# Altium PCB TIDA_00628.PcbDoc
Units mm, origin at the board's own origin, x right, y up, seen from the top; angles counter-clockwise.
Board outline 93.5 x 54.5 mm, 2 copper layers (Top Layer, Bottom Layer), stack 1.644 mm thick; 57 components, 18 nets, 97 pads, 0 vias.
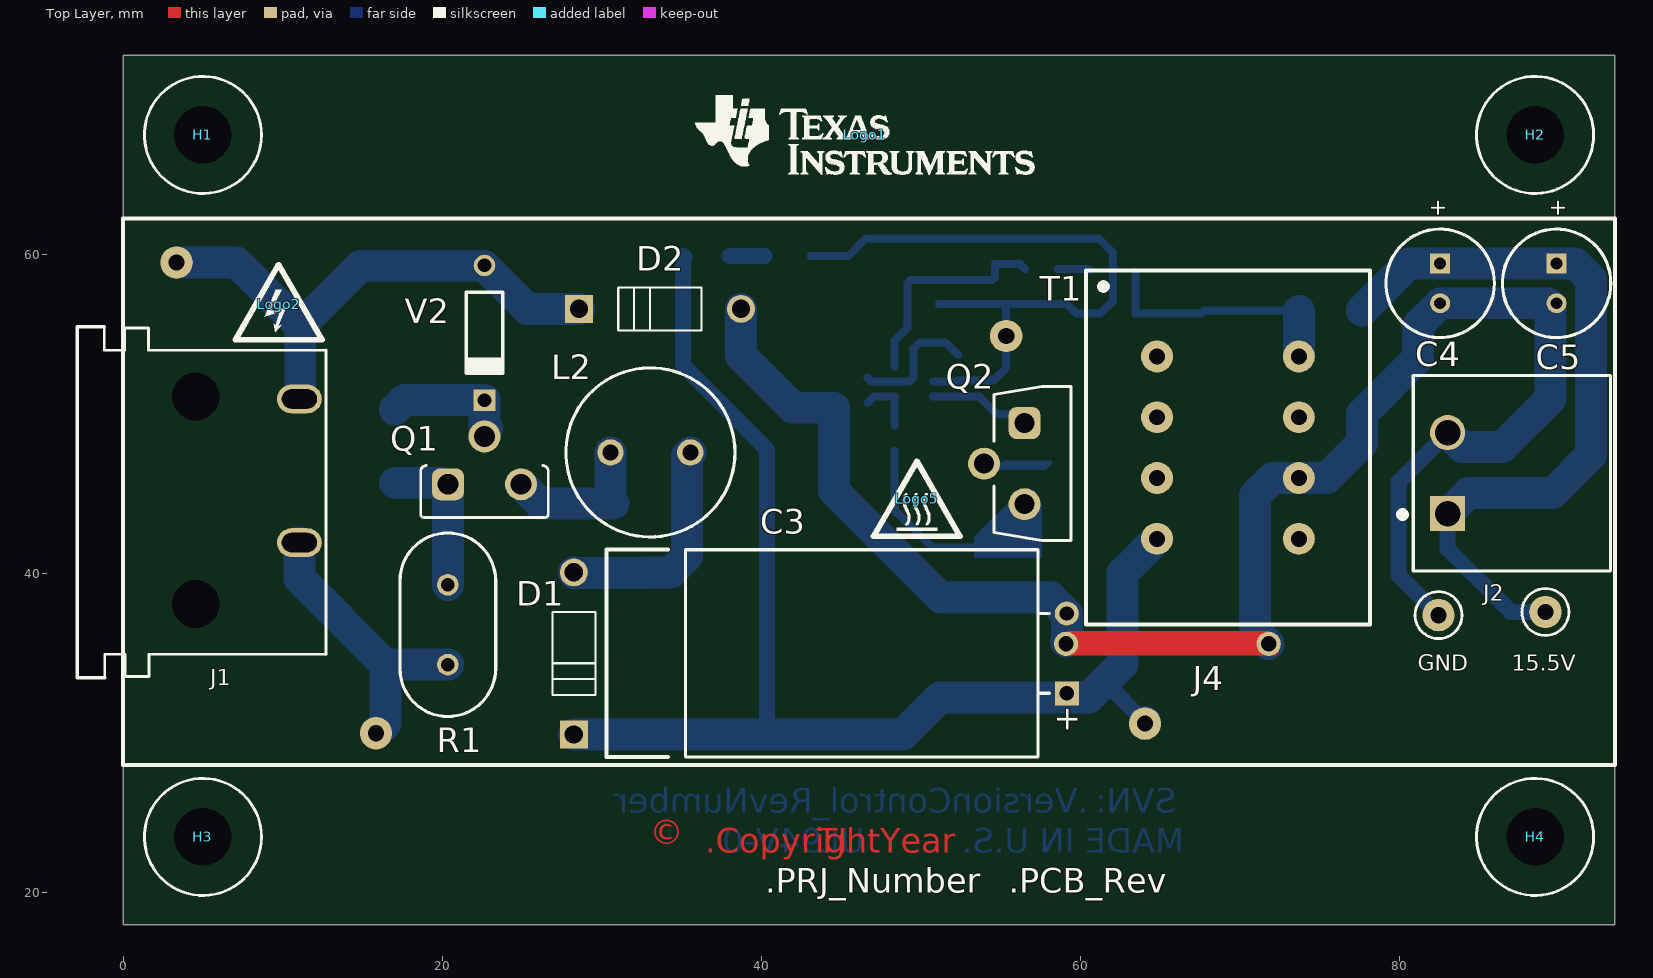
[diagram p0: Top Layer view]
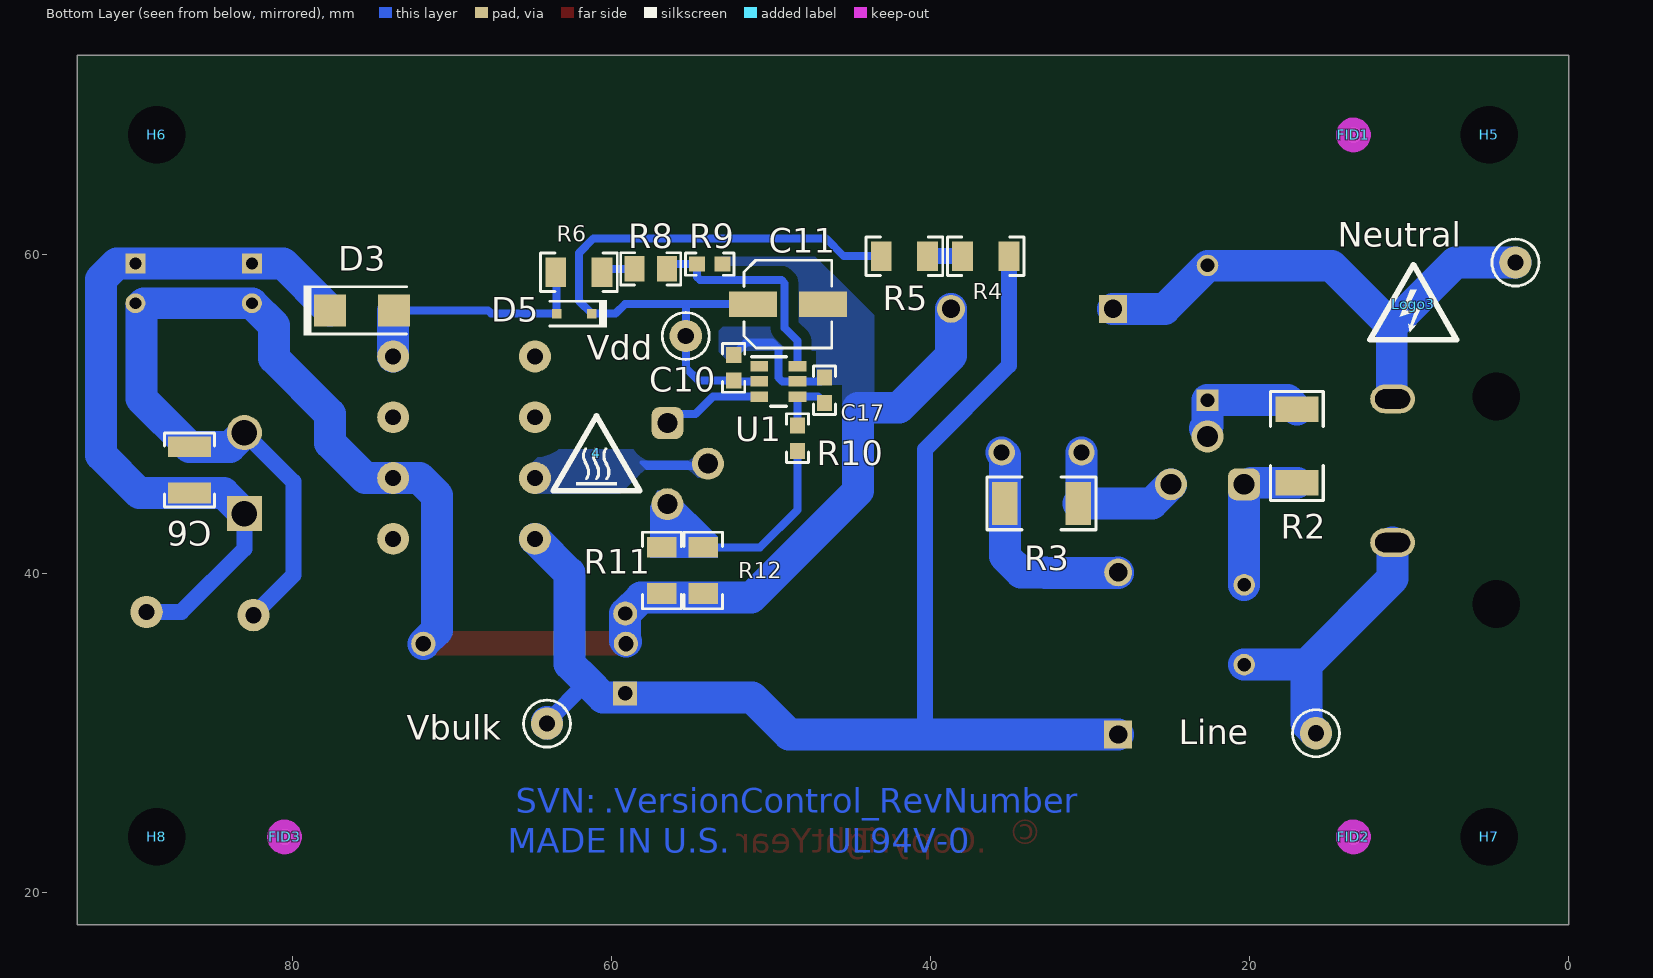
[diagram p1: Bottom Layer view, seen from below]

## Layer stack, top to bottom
Top Solder: solder mask 0.0102, Solder Resist, Dk 3.5
Top Layer: signal copper 0.07
Dielectric1: core 1.5037, FR-4, Dk 4.8
Bottom Layer: signal copper 0.07
Bottom Solder: solder mask 0.0102, Solder Resist, Dk 3.5

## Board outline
0,18 0,72.5 93.5,72.5 93.5,18

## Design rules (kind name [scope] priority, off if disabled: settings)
AcuteAngle [All] p1: minimum=4.50000000000000E+0001 checktracksonly=FALSE
AssemblyTestPointUsage [All] p1: valid=2
Clearance "Schematic Clearance Constraint_9" [InNet('NetD2_1')] p1: gap=2
Clearance "Schematic Clearance Constraint_4" [InNet('NetL2_1')] p2: gap=2
Clearance "Schematic Clearance Constraint_1" [InNet('NetQ1_1')] p3: gap=2
Clearance "Schematic Clearance Constraint" [InNet('NetC3_1')] p4: gap=1.5
Clearance "Schematic Clearance Constraint_6" [InNet('NetQ2_2')] p5: gap=1.5
Clearance "Schematic Clearance Constraint_5" [InNet('NetD1_2')] p6: gap=2
Clearance "Schematic Clearance Constraint_7" [InNet('NetQ1_2')] p7: gap=2
Clearance Clearance_Keepouts [((IsTrack Or IsArc) And Not InPoly) And IsFree and IsKeepOut vs ((IsTrack Or IsArc) And Not InPoly) And IsFree and IsKeepOut] p8: gap=0
Clearance Clearance_BoardEdge_MountingHoles [OnCopper and InComponentClass('Mounting Holes') vs IsKeepOut] p9: gap=1.016
Clearance Clearance_BoardEdge_Poly [OnCopper and InPoly vs IsKeepOut] p10: gap=0.635
Clearance Clearance_BoardEdge [OnCopper and Not InComponentClass('Logo') and not InComponentClass('FiducialMark') and not InRegion(1000,500,4000,800) and Not IsKeepout vs IsKeepOut] p11: gap=1.905
Clearance Clearance_Poly [InPolygon] p12: gap=0.635
Clearance [All] p13: gap=0.2
ComponentClearance ComponentClearance_MountingHoles_FiducialMarks [InComponentClass('Mounting Holes') vs InComponentClass('FiducialMark')] p1: gap=0.5 collisioncheckmode=3 verticalgap=0 showdistances=FALSE
ComponentClearance ComponentClearance_Shunt [InComponentClass('Header') vs InComponentClass('Shunt')] p2: gap=0 collisioncheckmode=3 verticalgap=0 showdistances=FALSE
ComponentClearance ComponentClearance_Logo [InComponentClass('Logo')] p3: gap=0.5 collisioncheckmode=3 verticalgap=0 showdistances=FALSE
ComponentClearance ComponentClearance_ScrewToNut [(HasFootprint('NY PMS 440 0025 PH')) vs (HasFootprint('Keystone_1902C'))] p4: gap=0 collisioncheckmode=3 verticalgap=0 showdistances=FALSE
ComponentClearance ComponentClearance_MountingHoles [InComponentClass('Mounting Holes')] p5: gap=0.5 collisioncheckmode=3 verticalgap=2540 showdistances=FALSE
ComponentClearance ComponentClearance_SmallPassives [HasFootprint('0201*') or HasFootprint('0402*') or HasFootprint('0508') or HasFootprint('0603*') or HasFootprint('0612') or HasFootprint('0805*') or HasFootprint('0815*') or HasFootprint('0830*') or HasFootprint('1206*') or HasFootprint('1210*') or HasFootprint('1808*') or HasFootprint('1812*') or HasFootprint('1825*') or HasFootprint('2010*') or HasFootprint('2220*') or HasFootprint('2225*') or HasFootprint('2512*') or HasFootprint('2728*') or HasFootprint('3518*') vs HasFootprint('0201*') or HasFootprint('0402*') or HasFootprint('0508') or HasFootprint('0603*') or HasFootprint('0612') or HasFootprint('0805*') or HasFootprint('0815*') or HasFootprint('0830*') or HasFootprint('1206*') or HasFootprint('1210*') or HasFootprint('1808*') or HasFootprint('1812*') or HasFootprint('1825*') or HasFootprint('2010*') or HasFootprint('2220*') or HasFootprint('2225*') or HasFootprint('2512*') or HasFootprint('2728*') or HasFootprint('3518*')] p6: gap=0.05 collisioncheckmode=3 verticalgap=0 showdistances=FALSE
ComponentClearance ComponentClearance_THtoSMT [IsThruComponent vs IsSMTComponent] p7: gap=0.1 collisioncheckmode=3 verticalgap=0 showdistances=FALSE
ComponentClearance ComponentClearance_THtoTH [IsThruComponent vs IsThruComponent] p8: gap=0.1 collisioncheckmode=3 verticalgap=0 showdistances=FALSE
ComponentClearance [All] p9: gap=0.05 collisioncheckmode=3 verticalgap=0 showdistances=FALSE
DiffPairsRouting [All] p1: maxlimit=2.54 minlimit=0.254 mostfreqgap=0.254 toplayer_minwidth=0.381 toplayer_maxwidth=0.381 toplayer_prefwidth=0.381 bottomlayer_minwidth=0.381 bottomlayer_maxwidth=0.381 bottomlayer_prefwidth=0.381 maxuncoupledlength=25.4
FabricationTestPointUsage TestPointUsage [All] p1: valid=2 allowmultiple=FALSE
FabricationTestpoint Testpoint [All] p1: side=3 testpointundercomponent=TRUE minsize=1.016 maxsize=2.54 preferedsize=1.524 minholesize=0 maxholesize=1.016 preferedholesize=0.813 testpointgrid=0.025 allowsidetop=TRUE allowsidebottom=TRUE usegrid=TRUE gridtolerance=0
FanoutControl Fanout_LCC [IsLCC] p1: bgadir=Out bgaviamode=Centered fanoutstyle=Auto fanoutdirection=Alternating viagrid=0.025 // Fanout_LCC (Default Rule)
FanoutControl Fanout_BGA [IsBGA] p2: bgadir=Out bgaviamode=Centered fanoutstyle=Auto fanoutdirection=Alternating viagrid=0.025 // Fanout_BGA (Default Rule)
FanoutControl Fanout_Default [All] p4: bgadir=Out bgaviamode=Centered fanoutstyle=Auto fanoutdirection=Alternating viagrid=0.025 // Fanout_Default (Default Rule)
FanoutControl Fanout_Small [(CompPinCount < 5)] p5: bgadir=Out bgaviamode=Centered fanoutstyle=Auto fanoutdirection=OutThenIn viagrid=0.025 // Fanout_Small (Default Rule)
HoleSize [All] p1: absolutevalues=TRUE maxlimit=6.375 minlimit=0.203 maxpercent=80.000 minpercent=20.000
MinimumAnnularRing MinimumAnnularRing_ThermalPadVias [IsVia and InAnyComponent] p1: minimumring=0.15
MinimumAnnularRing [All] p2: minimumring=0.229
MinimumSolderMaskSliver MinimumSolderMaskSliver_Logo [InComponentClass('Logo') vs InComponentClass('Logo')] p1: minsoldermaskwidth=0.018
MinimumSolderMaskSliver [All] p2: minsoldermaskwidth=0.1
PlaneConnect [All] p1: planeconnectstyle=Direct reliefexpansion=0.254 reliefentries=4 reliefconductorwidth=0.254 reliefairgap=0.254
PolygonConnect [All] p1: connectstyle=Direct reliefconductorwidth=0.254 reliefentries=4 polygonreliefangle="90 Angle" airgapwidth=0.254
RoutingVias ThermalPadVias [IsVia and InAnyComponent] p1: holewidth=0.2 width=0.5 viastyle="Through Hole" minholewidth=0.2 minwidth=0.5 maxholewidth=0.33 maxwidth=0.6
RoutingVias [All] p2: holewidth=0.406 width=0.864 viastyle="Through Hole" minholewidth=0.2 minwidth=0.66 maxholewidth=1.016 maxwidth=1.651
SilkToBoardRegionClearance [Not ((IsComment or IsDesignator) And (Hide <> 'False')) and not InRegion(1000,500,4000,800)] p1:
SilkToSilkClearance SilkToSilkClearance_Pb-FreeLogo [(HasFootprint('Pb-Free_Overlay_Medium') OR HasFootprint('Pb-Free_Overlay_Small')) vs (HasFootprint('Pb-Free_Overlay_Medium') OR HasFootprint('Pb-Free_Overlay_Small'))] p1: silktosilkclearance=0
SilkToSilkClearance [All] p2: silktosilkclearance=0.05
SilkToSolderMaskClearance "Silk to Solder Mask Opening" [All] p1: minsilkscreentomaskgap=0.025 clearancetoexposedcopper=FALSE
SolderMaskExpansion [All] p1: expansion=0.05
UnpouredPolygon [All] p1: allowunpoured=FALSE
Width [All] p1: maxlimit=2.54 minlimit=0.152 preferedwidth=0.254 checkconnectedcopper=TRUE
14 further rules are at their usual default settings.

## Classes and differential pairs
component class TIDA_00628: 15.5V C3 C4 C5 C6 C10 C11 C15 C17 D1 D2 D3 D5 GND J1 J2 J4 L2 Line Line1 Neutral Neutral1 Q1 Q2 R1 R2 R3 R4 R5 R6 R8 R9 R10 R11 R12 T1 U1 V2 Vbulk Vdd Vout_1.2 Vout_3.3 Vout_5.25 Vout_15.5
component class Logo: Logo1
component class TIDA_00628_Hardware: 4 FID1 FID2 FID3 H1 H2 H3 H4 H5 H6 H7 H8 Logo1 Logo2 Logo3 Logo5 ZZ1 ZZ2 ZZ3 ZZ4
component class FiducialMark: FID1 FID2 FID3
component class AssemblyNote: ZZ1 ZZ2 ZZ3 ZZ4

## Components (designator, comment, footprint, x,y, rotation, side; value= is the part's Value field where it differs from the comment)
4 "CAUTION HOT SURFACE" IEC_HotSurface_Small 60.95,47.55 r180 bottom
15.5V "5000" Keystone5000 89.15,37.6 r90 top
C3 "450BXW33MEFC12.5X25" CAPPR5-12.5X20_HorizontalUp 59.15,35 r90 top
C4 "EKYB250ELL151MF11D" ZLH_630x1100 82.55,58.2 r270 top
C5 "EKYB250ELL151MF11D" ZLH_630x1100 89.85,58.2 r270 top
C6 "GRM32ER71H106KA12L" 1210 86.45,46.5 r90 bottom
C10 "06035C104KAT2A" 0603 52.35,52.9 r90 bottom
C11 "UUD1V220MCL1GS" SM_RADIAL_5MM 48.95,56.9 r180 bottom
C17 "06033C101KAT2A" 0603 46.65,51.5 r90 bottom
D1 "1N4007" DO-41 28.25,35 r90 top
D2 "1N4007" DO-41 33.65,56.6 r0 top
D3 "STPS1150A" SMA 75.65,56.5 r180 bottom
D5 "BAS20-V" sod-323 62.35,56.3 r0 bottom
FID1 "Fiducial" Fiducial10-20 13.5,67.5 r180 bottom
FID2 "Fiducial" Fiducial10-20 13.5,23.5 r180 bottom
FID3 "Fiducial" Fiducial10-20 80.5,23.5 r180 bottom
GND "5001" Keystone5001 82.45,37.4 r90 top
H1 "4820" KEYSTONE_4820 5,67.5 r0 top locked
H2 "4820" KEYSTONE_4820 88.5,67.5 r0 top locked
H3 "4820" KEYSTONE_4820 5,23.5 r0 top locked
H4 "4820" KEYSTONE_4820 88.5,23.5 r0 top locked
H5 "1903E" KEYSTONE_1903E 5,67.5 r180 bottom locked
H6 "1903E" KEYSTONE_1903E 88.5,67.5 r180 bottom locked
H7 "1903E" KEYSTONE_1903E 5,23.5 r180 bottom locked
H8 "1903E" KEYSTONE_1903E 88.5,23.5 r180 bottom locked
J1 "770W-X2/10" CONN_AC_770W-SERIES 7.75,44.6 r90 top
J2 "20020110-H021A01LF" FCI_20020110-H021A01LF 87.05,46.3 r90 top
J4 "923345-05-C" 923345-05-C 65.45,35.6 r180 top
L2 "744743102" WE-TI_1014 33.05,47.6 r0 top
Line "5000" Keystone5000 15.85,30 r90 bottom
Logo1 "Texas Instruments" TI_Stacked_Overlay_Small 46.5,67.5 r0 top
Logo2 "DANGER HIGH VOLTAGE" IEC_HighVoltage_Small 9.75,56.9 r0 top
Logo3 "DANGER HIGH VOLTAGE" IEC_HighVoltage_Small 9.75,56.9 r180 bottom
Logo5 "CAUTION HOT SURFACE" IEC_HotSurface_Small 49.75,44.7 r0 top
Neutral "5001" Keystone5001 3.35,59.5 r90 bottom
Q1 "FQPF2N80" SOT-32 22.65,45.6 r0 top
Q2 "BUJ302AX" TO-220_FullPAK_Offset 56.5,46.9 r270 top
R1 "B57236S0100M000" THERM_B57236S0 20.35,36.8 r90 top
R2 "CRCW2010100KJNEF" 2010 17.05,48 r270 bottom
R3 "CRCW20106K80JNEF" 2010 33.05,44.4 r0 bottom
R4 "CRCW1206270KJNEA" 1206 36.55,59.9 r180 bottom
R5 "CRCW1206270KJNEA" 1206 41.65,59.9 r180 bottom
R6 "CRCW12060000Z0EA" 1206 62.05,58.9 r0 bottom
R8 "CRCW0805115KFKEA" 0805_HV 57.55,59.1 r0 bottom
R9 "RC0603FR-0740K2L" 0603 53.85,59.4 r0 bottom
R10 "CRCW06033K09FKEA" 0603 48.35,48.5 r270 bottom
R11 "RC1206FR-072R7L" 1206 56.85,40.2 r90 bottom
R12 "RC1206FR-072R7L" 1206 54.25,40.2 r90 bottom
T1 "Used in BOM report" XFMR-EF16-V 69.25,47.9 r0 top
U1 "UCC28722DBV" DBV0006A_N 49.55,52.05 r180 bottom
V2 "P6KE400CARL" DO-35 22.65,55.1 r90 top
Vbulk "5004" Keystone5004 64.05,30.6 r180 bottom
Vdd "5004" Keystone5004 55.35,54.9 r180 bottom
ZZ1 "This Assembly Note is for PCB labels only" AssemblyNoteLabel -12.15,99.2 r0 top
ZZ2 "These assemblies are ESD sensitive, ESD precautions shall be observed." AssemblyNote -12.151,97.26 r0 top
ZZ3 "These assemblies must be clean and free from flux and all contaminants. Use of no clean flux is not acceptable." AssemblyNote -12.151,95.01 r0 top
ZZ4 "These assemblies must comply with workmanship standards IPC-A-610 Class 2, unless otherwise specified." AssemblyNote -12.151,92.761 r0 top

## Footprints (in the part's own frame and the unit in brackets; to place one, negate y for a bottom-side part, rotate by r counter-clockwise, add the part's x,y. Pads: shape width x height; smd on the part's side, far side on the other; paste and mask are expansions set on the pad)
0603 [mm] "0603 from SM-752 data"
  rect 1x0.95 smd: 1(-0.8,0) 2(0.8,0)
  silkscreen extent -1.52,-0.69 1.52,0.69, body extent -0.87,-0.47 0.87,0.47, height 0.85
0805_HV [mil] "0805 with 30mil clearance between pads"
  rect 50x63 smd: 1(-40,0) 2(40,0)
  silkscreen extent -74,-40 74,40, body extent -43,-29 43,29, height 57
1206 [mm] "1206 from SM-752 data"
  rect 1.3x1.85 smd: 1(-1.45,0) 2(1.45,0)
  silkscreen extent -2.4,-1.21 2.4,1.21, body extent -1.7,-0.9 1.7,0.9, height 1.35
1210 [mm] "1210 from SM-752 data"
  rect 1.3x2.7 smd: 1(-1.45,0) 2(1.45,0)
  silkscreen extent -2.32,-1.57 2.32,1.57, body extent -1.7,-1.35 1.7,1.35, height 1.35
2010 [mm] "Chip Capacitor, Body 5.08x2.54mm, IPC Medium Density"
  rect 1.6x2.7 smd: 1(-2.3,0) 2(2.3,0)
  silkscreen extent -3.42,-1.65 3.42,1.65, body extent -2.73,-1.45 2.73,1.45, height 1.66
923345-05-C [mil] "Wire Jumper 500mil"
  round 60 hole 38: 1(-250,0) 2(250,0)
  body extent -263,-33 263,33, height 71
AssemblyNote [mm] "Assembly Note"
AssemblyNoteLabel [mm] "Assembly Note for PCB Labels"
CAPPR5-12.5X20_HorizontalUp [mm] "Capacitor, Electrolytic, Radial; Body 12.5 x 20 mm (Dia.xH typ); Pin Spacing 5 mm (typ)"
  rect 1.5x1.5 hole 0.9: 1(-2.5,0)
  round 1.5 hole 0.9: 2(2.5,0)
  silkscreen extent -6.5,1.1 6.5,23.9, body extent -6.47,-0.3 6.47,23.85, height 12.99
CONN_AC_770W-SERIES [mm] "Qualtek Electronics"
  oval 1.8x2.8 hole 1.2 slot 2.2 at 90 deg: 1(6.35,-3.3) 2(-2.65,-3.3)
  round 2 hole 3 unplated: MH1(6.5,3.2) MH2(-6.5,3.2)
  silkscreen extent -11.12,-4.97 10.87,10.63, body extent -11.05,-4.8 10.8,10.6, height 22
DBV0006A_N [mm] "SOT23, 6-Leads, Body 2.9x1.6mm, Pitch 0.95mm, Lead Span 2.8mm, IPC Medium Density"
  rect 1.1x0.65 smd: 1(-1.2,0.95) 2(-1.2,0) 3(-1.2,-0.95) 4(1.2,-0.95) 5(1.2,0) 6(1.2,0.95)
  silkscreen extent -1.68,-1.55 0.5,1.55, body extent -1.42,-1.46 1.42,1.46, height 1.11
DO-35 [mm] "TH, 2-Leads, Axial, Pin spacing 8.44mm"
  rect 1.35x1.35 hole 0.85: 1(-4.22,0)
  round 1.35 hole 0.85: 2(4.22,0)
  silkscreen extent -2.54,-1.15 2.54,1.15, body extent -4.5,-1.15 4.5,1.15, height 2.29
DO-41 [mm] "diode"
  rect 1.75x1.75 hole 1.15: 1(-5.08,0)
  round 1.75 hole 1.15: 2(5.08,0)
  silkscreen extent -2.62,-1.37 2.59,1.35, body extent -5.51,-1.36 5.51,1.36, height 2.72
FCI_20020110-H021A01LF [mm] "FCI"
  rect 2.2x2.2 hole 1.6 paste+0 mask+0.05: 1(-2.54,4.03)
  round 2.2 hole 1.6 paste+0 mask+0.05: 2(2.54,4.03)
  silkscreen extent -6.13,-6.18 6.13,7.06, body extent -6.08,-6 6.08,6, height 8.67
Fiducial10-20 [mm]
  round 1 smd mask+0.5: 1(0,0)
  Top Layer keep-out circle w1.178: c0,0 r0.5
IEC_HighVoltage_Small [mm]
  silkscreen extent -2.72,-2.24 2.72,2.47
IEC_HotSurface_Small [mm]
  silkscreen extent -2.72,-2.36 2.72,2.35
Keystone5000 [mil] "For Keystone 500x miniature loop terminals"
  round 80 hole 40: 1(0,0)
  silkscreen extent -58,-58 58,58, body extent -49,-49 49,49, height 182
Keystone5001 [mil] "For Keystone 500x miniature loop terminals"
  round 80 hole 40: 1(0,0)
  silkscreen extent -58,-58 58,58, body extent -49,-49 49,49, height 182
Keystone5004 [mil] "For Keystone 500x miniature loop terminals"
  round 80 hole 40: 1(0,0)
  silkscreen extent -58,-58 58,58, body extent -49,-49 49,49, height 182
KEYSTONE_1903E [mil] "HEX NYLON STANDOFF 6-32, F-F 1\""
  round 1 on Mech4: 0(0,0)
  body extent -148,-128 148,128, height 1000
KEYSTONE_4820 [mm] "HEX NYLON STANDOFF 6-32, M-F 1\""
  round 0.025 on Mech3: 0(0,0)
  round 1 hole 3.6 unplated: MH(0,0)
  silkscreen extent -3.67,-3.67 3.67,3.67, body extent -3.67,-3.17 3.67,3.18, height 25.42
SM_RADIAL_5MM [mm] "Nichicon 5x5.8"
  rect 3x1.6 smd: 1(-2.2,0) 2(2.2,0)
  silkscreen extent -2.75,-2.75 2.75,2.75, body extent -2.75,-2.75 2.75,2.75, height 6.1
SMA [mm] "Molded Diode, 2-Leads, Body 4.3x2.6mm, IPC Medium Density, based on OnSemi component dimensions and land pattern"
  rect 2x2 smd: 1(-2,0) 2(2,0)
  silkscreen extent -3.66,-1.57 2.79,1.57, body extent -2.6,-1.3 2.6,1.3, height 2.42
sod-323 [mm] "NXP recommended land pattern"
  rect 0.6x0.6 smd paste-0.05: 1(-1.1,0) 2(1.1,0)
  silkscreen extent -2.06,-0.86 1.53,0.86, body extent -1.3,-0.67 1.3,0.68, height 1.1
SOT-32 [mm]
  rrect50% 2x2 hole 1.3: 1(-2.29,0)
  round 2 hole 1.3: 2(0,3) 3(2.29,0)
  silkscreen extent -4,-2.08 4,1.18, body extent -4,-2.07 4,1.18, height 13.13
THERM_B57236S0 [mm] "EPCOS"
  round 1.35 hole 0.85: 1(-2.5,0) 2(2.5,0)
  silkscreen extent -5.75,-3 5.75,3, body extent -5.75,-3 5.7,3, height 15.99
TI_Stacked_Overlay_Small [mm]
  silkscreen extent -10.63,-2.49 10.63,2.49
TO-220_FullPAK_Offset [mm] "Infineon  PG-TO220-3-31"
  rrect50% 2x2 hole 1.27: 1(-2.54,0)
  round 2 hole 1.27: 2(0,-2.54) 3(2.54,0)
  silkscreen extent -4.82,-1.91 4.83,2.92, body extent -4.82,-2.84 4.83,2.92, height 22.91
WE-TI_1014 [mm] "WURTH"
  round 1.65 hole 1: 1(-2.5,0) 2(2.5,0)
  silkscreen extent -5.3,-5.3 5.3,5.3, body extent -5.26,-5.26 5.26,5.26, height 14.5
XFMR-EF16-V [mm]
  round 2 hole 1: 1(-4.445,5.715) 2(-4.445,1.905) 3(-4.445,-1.905) 4(-4.445,-5.715) 5(4.445,-5.715) 6(4.445,-1.905) 7(4.445,1.905) 8(4.445,5.715)
  silkscreen extent -8.89,-11.1 8.89,11.1
ZLH_630x1100 [mm] "Radial Leaded, 2-Leads, Dia 6.3mm, Height 11mm, Pin Spacing 2.5mm"
  rect 1.25x1.25 hole 0.75: 1(-1.25,0)
  round 1.25 hole 0.75: 2(1.25,0)
  silkscreen extent -3.4,-3.4 3.4,3.4, body extent -3.37,-3.39 3.4,3.39, height 12.51

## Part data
4 Logo5: library part IEC_HotSurface, "IEC 61010-1 Hot Surface Warning"
15.5V Line: "Test Point, TH, Miniature, Red"
C3: library part Capacitor_Polarized, "CAP, [Technology], xxxF, xxV, +/-xx%, xxOhm ESR, [MountType]"
C4 C5: library part Capacitor_Polarized, "CAP ALUM 150UF 20% 25V RADIAL"
C6: "CAP, CERM, 10uF, 50V, +/-10%, X7R, 1210"
C10: "CAP, CERM, 0.1uF, 50V, +/-10%, X7R, 0603"
C11: "CAP, AL, 22 µF, 35 V, +/- 20%, 0.76 ohm, SMD"
C17: "CAP, CERM, 100 pF, 25 V, +/- 10%, X7R, 0603"
D1 D2: "Diode, P-N, 1000V, 1A, TH"
D3: library part STPS130A, "Diode, Schottky, 150V, 1A, SMA"
D5: library part BAS316,115, "DIODE SWITCH 200V 200MA SOD323"
FID1 FID2 FID3: "Fiducial mark.  There is nothing to buy or mount."
GND Neutral: "Test Point, TH, Miniature, Black"
H1 H2 H3 H4: "Standoff, Hex, 1\"L #6-32 Nylon, M-F"
H5 H6 H7 H8: "Standoff, Hex, 1\"L #6-32 Nylon"
J1: "AC Receptacle, 2.5A, R/A, TH"
J2: "Terminal Block, 2x1, 5.08mm, TH"
J4: "Jumper Wire, 500mil spacing, Green, pkg of 200"
L2: library part 7447480101, "Inductor, Wirewound, Ferrite, 1000uH, 0.42A, 2.5 ohm, TH"
Logo1: library part TI_Logo, "Texas Instrument Corporate Signature"
Logo2 Logo3: library part IEC_HighVoltage, "IEC 61010-1 High Voltage Warning"
Q1: library part MOSFET_N, "MOSFET N-CH 800V 1.5A TO-220F"
Q2: library part BJT_NPN_C3B1E2, "Transistor, NPN, xxV, 4A, TO-220F"
R1: "Thermistor NTC, 10 ohm, 20%, Disc_11.5mmx6mm"
R2: "RES, 100 k, 5%, 0.75 W, 2010"
R3: "RES, 6.8 k, 5%, 0.75 W, 2010"
R4 R5: "RES, 270 k, 5%, 0.25 W, 1206"
R6: "RES, 0, 5%, 0.25 W, 1206"
R8: "RES, 115 k, 1%, 0.125 W, 0805"
R9: "RES, 40.2 k, 1%, 0.1 W, 0603"
R10: "RES, 3.09 k, 1%, 0.1 W, 0603"
R11 R12: "RES, 2.70, 1%, 0.25 W, 1206"
T1: library part XFMR_1_4_INV, "1 Input 4 Output XFMR"
U1: "Constant-Voltage, Constant-Current Controller With Primary-Side Regulation, BJT Drive, DBV0006A"
V2: library part TVS_Diode, "TVS DIODE 342VWM 706VC DO15"
Vbulk Vdd: "Test Point, Miniature, Yellow, TH"
ZZ1: library part AssemblyNoteLabel
ZZ2 ZZ3 ZZ4: library part AssemblyNote

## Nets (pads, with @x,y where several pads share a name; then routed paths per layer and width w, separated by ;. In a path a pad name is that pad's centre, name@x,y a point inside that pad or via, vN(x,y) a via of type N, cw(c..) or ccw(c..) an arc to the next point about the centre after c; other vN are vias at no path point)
GND: C3.2 C4.2 C5.2 C6.2 C10.2 C11.2 C17.2 D2.2 GND.1 J2.2 J4.1 J4.2 R9.1 R11.1 R12.1 T1.6 U1.5 | length 106.2
  Bottom Layer w0.5: C17.2 46.9,52.05 U1.5 49.3,52.05 49.55,52.3 49.55,54.1 49.95,54.5 51.55,54.5 C10.2
  Bottom Layer w1: GND.1 79.95,39.9 79.95,45.77 J2.2
  Bottom Layer w2: D2.2 38.73,53.663 41.993,50.4 44.55,50.4 44.55,45.2 51.25,38.5 58.15,38.5 C3.2 59.15,35.8 J4.2@59.1,35.75 ; J4.1 70.95,36.45 70.95,44.9 72.045,45.995 T1.6 75.445,45.995 77.65,48.2 77.65,50 81.15,53.5 81.15,55.55 C4.2 89.32,56.95 89.475,56.795 89.475,50.975 C6.2 83.91,47.95 J2.2
NetC3_1: C3.1 D1.1 R4.2 T1.4 Vbulk.1 | length 80.9
  Bottom Layer w1: R4.2@35.18,59.82 R4.2 35.1,53.05 40.35,47.8 40.35,29.92 ; 61.55,33.25 61.55,33.2 Vbulk.1@64.05,30.7
  Bottom Layer w2: D1.1 40.35,29.92 48.87,29.92 51.2,32.25 60.55,32.25 61.55,33.25 62.65,34.35 62.65,40.03 T1.4 ; Vbulk.1 Vbulk.1@64.05,30.7
NetC10_1: C10.1 C11.1 D5.1 R5.1 U1.2 Vdd.1 | length 43.2
  Bottom Layer w0.5: R5.1 45.45,59.9 46.55,61 61.15,61 62.05,60.1 62.05,57.1 D5.1 59.75,56.3 59.15,56.9 55.35,56.9 ; U1.2 52.3,52.05 C10.1 54.55,52.1 55.35,52.9 Vdd.1 55.35,56.9 ; C11.1 55.35,56.9
NetC17_1: C17.1 R10.1 U1.4 | length 3.7
  Bottom Layer w0.5: C17.1 47.05,51.1 U1.4 R10.1
NetD1_2: D1.2 L2.2 R3.2 | length 14.1
  Bottom Layer w2: D1.2 28.25,40.05 32.793,40.05 32.823,40.08 34.33,40.08 35.35,41.1 R3.2 35.35,47.4 L2.2
NetD2_1: D2.1 J1.1 Neutral.1 V2.2 | length 33.8
  Bottom Layer w2: Neutral.1 7.122,59.5 11.1,55.522 ; J1.1@11.1,51.25 11.1,55.522 ; D2.1 25.33,56.6 22.63,59.3 14.878,59.3 11.1,55.522
NetJ1_2: J1.2 Line.1 R1.1 | length 18.3
  Bottom Layer w2: J1.2 11.05,39.7 16.45,34.3 ; Line.1 16.45,30.6 16.45,34.3 ; R1.1 16.45,34.3
NetL2_1: L2.1 Q1.3 R3.1 | length 9.6
  Bottom Layer w2: Q1.3 26.14,44.4 R3.1 30.55,44.6 L2.1
NetQ1_1: Q1.1 R1.2 R2.2 | length 9.4
  Bottom Layer w2: R2.2 19.893,45.7 20.35,45.243 R1.2
NetQ1_2: Q1.2 R2.1 V2.1 | length 7.7
  Bottom Layer w2: R2.1 17.63,50.88 V2.1 22.65,49.26 Q1.2@22.796,49.113
NetQ2_1: Q2.1 U1.3 | length 6.4
  Bottom Layer w0.5: U1.3 53.65,51.1 54.75,50 55.94,50 Q2.1
NetQ2_2: Q2.2 T1.3
NetQ2_3: Q2.3 R10.2 R11.2 R12.2 | length 10.6
  Bottom Layer w0.5: R10.2 48.35,44 50.7,41.65 R12.2
NetR4_1: R4.1 R5.2 | length 2.2
  Bottom Layer w1: R4.1 R5.2
NetR6_1: R6.1 R8.2 | length 2.1
  Bottom Layer w0.5: R8.2 60.5,59.1 R6.1@60.6,59
NetR8_1: R8.1 R9.2 U1.6 | length 14
  Bottom Layer w0.5: U1.6 48.35,54.6 49.15,55.4 49.15,58.2 49.35,58.4 54.45,58.4 54.65,58.6 R9.2 56.234,59.4 R8.1
VOUT_15: 15.5V.1 C4.1 C5.1 C6.1 D3.1 J2.1 | length 47.5
  Bottom Layer w1: J2.1 83.02,41.546 86.966,37.6 15.5V.1
  Bottom Layer w2: D3.1 80.6,59.45 C4.1 C5.1 91,59.45 92,58.45 92,47.45 89.6,45.05 C6.1 84.31,45.05 J2.1
VSEC: D3.2 D5.2 R6.2 T1.8 | length 15.8
  Bottom Layer w0.5: R6.2@63.45,58.95 D5.2 67.55,56.3 67.75,56.5 D3.2
  Bottom Layer w2: T1.8 D3.2@73.695,56.455
pads on no net: FID1.1 FID2.1 FID3.1 H1.0 H1.MH H2.0 H2.MH H3.0 H3.MH H4.0 H4.MH H5.0 H6.0 H7.0 H8.0 J1.MH1 J1.MH2 T1.1 T1.2 T1.5 T1.7 U1.1

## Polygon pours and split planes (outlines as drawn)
NetQ2_2 on Bottom Layer "Bottom Layer-No Net 1" (solid, remove dead copper, pour order 3): 53.95,47.8 64.15,47.8 65.35,46.6 65.35,45.4 65.15,45.2 64.95,45 61.85,45 59.45,45 58.45,46 55.95,46 54.05,46 53.25,46.8
GND on Bottom Layer "Bottom Layer-No Net" (solid, remove dead copper, pour order 2): 43.55,50 49.375,50 52.825,53.45 53.3,53.925 53.3,59.875 47.225,59.875 45.05,57.7 43.55,56.2

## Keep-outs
Keep-Out Layer:
  text ".Layer_Name" at -2.194,-21.806 h1.52

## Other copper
Top Layer:
  region net GND: 59.05,34.9 72.25,34.9 72.45,35.1 72.45,35.8 71.85,36.4 59.25,36.4 59.05,36.2
  text "©" at 33,22.5 h2.67
  text ".CopyrightYear" at 36.49,22.5 h1.52
  text "TI" at 43.5,22.5 h1.52
  text ".Layer_Name" at -2.194,-21.806 h1.52
Bottom Layer:
  region net NetQ2_2: 55.231,47.083 58.167,47.083 58.25,47 58.25,46.934 57.845,46.529 54.856,46.529 54.585,46.8
  region net NetQ2_3: 57.15,45.2 56.25,45.2 53.35,42.3 53.35,41.001 57.585,41.001 57.585,44.2
  text ".VersionControl_RevNumber" at 60.5,25 h1.52
  text "SVN:" at 66,25 h1.52
  text "UL94V-0" at 46.5,22.5 h1.52
  text "MADE IN U.S." at 66.5,22.5 h1.52
  text ".Layer_Name" at -2.194,-21.806 h1.52

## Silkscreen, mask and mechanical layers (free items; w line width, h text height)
Top Overlay:
  lines w0.25: 34.15,28.5 30.3,28.5 30.3,41.5 34.15,41.5 ; 0,28 0,62.25 93.5,62.25 93.5,28 0,28
  text ".PRJ_Number" at 40.26,20 h1.52
  text ".PCB_Rev" at 55.5,20 h1.52
  text ".Layer_Name" at -2.194,-21.806 h1.52
Bottom Overlay:
  text ".Layer_Name" at -2.194,-21.806 h1.52
Top Paste:
  text ".Layer_Name" at -2.194,-21.806 h1.52
Bottom Paste:
  text ".Layer_Name" at -2.194,-21.806 h1.52
Top Solder:
  text ".Layer_Name" at -2.194,-21.806 h1.52
  text ".Layer_Name" at -2.194,-21.806 h1.52
Bottom Solder:
  text ".Layer_Name" at -2.194,-21.806 h1.52
Drill Guide:
  text ".Layer_Name" at -2.194,-21.806 h1.52
M1 Board Outline:
  the board outline again, w0.254
  text ".Layer_Name" at -2.194,-21.806 h1.52
M2 Board Dimensions:
  rectangle: -16.85,-6.985 -13.675,-3.81
  rectangle: -13.675,-10.16 -4.15,-6.985
  lines w0.178: -16.85,-6.985 8.55,-6.985 ; -13.675,-10.16 -13.675,-3.81 ; -10.5,-10.16 -10.5,-3.81 ; -4.15,-10.16 -4.15,-3.81 ; 2.2,-10.16 2.2,-3.81 ; -16.85,-10.16 8.55,-10.16 8.55,-3.81 -16.85,-3.81 -16.85,-10.16
  text ".Layer_Name" at -2.194,-21.806 h1.52
M3 3D STEP Top:
  text ".Layer_Name" at -2.194,-21.806 h1.52
M4 3D STEP Bottom:
  text ".Layer_Name" at -2.194,-21.806 h1.52
M5 Assembly Top:
  lines w0.254: -24.267,-23.626 143.373,-23.626 ; -24.267,-18.462 143.424,-18.462 ; -24.267,-13.297 -24.267,-28.791 77.46,-28.791 143.424,-28.791 143.424,-13.297 -24.254,-13.297 -24.254,-28.791 15.764,-28.791 ; 38.344,-28.791 38.344,-13.297 ; 70.526,-18.462 70.526,-13.297 ; 91.862,-18.462 91.862,-13.297 ; 107.661,-28.956 107.661,-23.804
  text "COMPONENTS MARKED 'DNP' SHOULD NOT BE POPULATED." at 12.449,-8.09 h1.52
  text "ASSEMBLY VARIANT:" at 12.436,-11.024 h1.52
  text ".VariantName" at 38.751,-11.024 h1.52
  text "PCB VIEWED FROM TOP SIDE" at -22.654,-16.654 h1.52
  text "BOARD #:" at 40.249,-16.654 h1.52
  text ".PRJ_Number" at 54.105,-16.654 h1.52
  text "REV:" at 75.555,-16.654 h1.52
  text ".PCB_Rev" at 82.959,-16.654 h1.52
  text "SVN REV:" at 96.84,-16.654 h1.52
  text ".VersionControl_RevNumber" at 109.693,-16.654 h1.52
  text "PLOT NAME =" at -22.654,-27.034 h1.52
  text ".plot_File_Name" at -2.194,-27.034 h1.52
  text "GENERATED    :" at 40.3,-27.034 h1.52
  text ".Print_Date" at 62.385,-27.034 h1.52
  text ".Print_Time" at 80.902,-27.034 h1.52
  text "TEXAS INSTRUMENTS" at 113.02,-27.034 h1.52
M6 Assembly Bottom:
  lines w0.254: -24.279,-18.474 143.411,-18.474 ; -24.229,-23.639 143.411,-23.639 ; 11.484,-28.969 11.484,-23.817 ; 27.283,-18.474 27.283,-13.31 ; 48.619,-18.474 48.619,-13.31 ; 80.8,-28.804 80.8,-13.31 ; 103.381,-28.804 143.399,-28.804 143.399,-13.31 -24.279,-13.31 -24.279,-28.804 41.684,-28.804 143.411,-28.804 143.411,-13.31
  text "COMPONENTS MARKED 'DNP' SHOULD NOT BE POPULATED." at 138.141,-8.077 h1.52
  text ".VariantName" at 111.623,-11.024 h1.52
  text "ASSEMBLY VARIANT:" at 138.014,-11.024 h1.52
  text ".VersionControl_RevNumber" at 9.452,-16.667 h1.52
  text "SVN REV:" at 22.304,-16.667 h1.52
  text ".PCB_Rev" at 36.185,-16.667 h1.52
  text "REV:" at 43.589,-16.667 h1.52
  text ".PRJ_Number" at 65.04,-16.667 h1.52
  text "BOARD #:" at 78.895,-16.667 h1.52
  text "PCB VIEWED FROM BOTTOM SIDE" at 141.798,-16.667 h1.52
  text "TEXAS INSTRUMENTS" at 6.124,-27.047 h1.52
  text ".Print_Time" at 38.243,-27.047 h1.52
  text ".Print_Date" at 56.759,-27.047 h1.52
  text "GENERATED    :" at 78.845,-27.047 h1.52
  text ".plot_File_Name" at 121.339,-27.047 h1.52
  text "PLOT NAME =" at 141.798,-27.047 h1.52
M9 Title Sheet:
  drawing of 57 lines, arcs and shapes, not listed
  text "1" at 1.942,204.127 h1.78
  text "2" at 65.332,204.127 h1.78
  text "3" at 128.561,204.127 h1.78
  text "4" at 192.23,204.127 h1.78
  text "5" at 255.705,204.127 h1.78
  text "6" at 319.332,204.127 h1.78
  text "A" at -27.429,175.095 h1.78
  text "A" at 348.491,175.095 h1.78
  text "B" at -27.429,114.643 h1.78
  text "B" at 348.491,114.643 h1.78
  text "C" at -27.429,54.318 h1.78
  text "C" at 348.491,54.318 h1.78
  text "PROJECT TITLE:" at 271.275,7.049 h1.14
  text ".PRJ_Title" at 272.545,3.662 h1.78
  text "DESIGNED FOR:" at 271.275,-0.597 h1.14
  text ".PRJ_Customer" at 272.545,-4.153 h1.78
  text "D" at -27.429,-5.88 h1.78
  text "D" at 348.491,-5.88 h1.78
  text "FILE NAME:" at 271.275,-8.217 h1.14
  text ".PCB_File_Name_No_Path" at 272.545,-11.265 h1.78
  text "Texas Instruments (TI) and/or its licensors do not warrant the accuracy or completeness of this specification" at 145.05,-15.376 h1.14
  text "ENGINEER:" at 271.275,-15.583 h1.14
  text "LAYOUT BY:" at 309.502,-15.583 h1.14
  text "or any information contained therein. TI and/or its licensors do not warrant that this design will meet" at 143.907,-18.237 h1.14
  text ".PRJ_Engineer" at 272.545,-19.52 h1.78
  text ".PCB_Layout" at 310.785,-19.52 h1.78
  text "the specifications, will be suitable for your application or fit for any particular purpose, or will operate in" at 143.907,-21.099 h1.14
  text ".Layer_Name" at -2.194,-21.806 h1.52
  text "ALTIUM DESIGNER VERSION:" at 309.502,-23.457 h1.14
  text "an implementation. TI and/or its licensors do not warrant that the design is production worthy. You should" at 143.907,-23.961 h1.14
  text "completely validate and test your design implementation to confirm the system functionality for your application." at 145.05,-26.822 h1.14
  text ".print_Scale" at 272.545,-26.843 h1.78
  text ".Application_BuildNumber" at 310.785,-26.843 h1.78
  text "1" at 1.942,-32.093 h1.78
  text "2" at 65.332,-32.093 h1.78
  text "3" at 128.561,-32.093 h1.78
  text "4" at 192.23,-32.093 h1.78
  text "5" at 255.705,-32.093 h1.78
  text "6" at 319.332,-32.093 h1.78
M10 Fab Notes:
  drawing of 185 lines, arcs and shapes, not listed
  text "DESIGN INFORMATION" at 297.628,150.114 h1.52
  text "MIN. TRACK WIDTH:" at 281.256,145.542 h1.52
  text "8" at 309.101,145.542 h1.52
  text "MIL" at 313.031,145.542 h1.52
  text "MIN. CLEARANCE:" at 281.256,142.189 h1.52
  text "0.2" at 307.577,142.189 h1.52
  text "mm" at 313.031,142.189 h1.52
  text "MIN. VIA PAD SIZE:" at 281.256,138.836 h1.52
  text "24" at 308.339,138.836 h1.52
  text "MIL" at 313.031,138.836 h1.52
  text "0.05mm (2MIL)" at 298.909,135.237 h1.52
  text "MINIMUM ANNULAR RING" at 272.894,135.128 h1.52
  text "EXTERNAL" at 316.892,135.128 h1.52
  text "PER" at 277.974,132.131 h1.52
  text "IPC-D-275 CLASS 2 LEVEL C" at 283.562,132.131 h1.52
  text "MIL, HOLES" at 321.363,129.279 h1.52
  text "+/-" at 311.394,129.261 h1.52
  text "+/-" at 333.086,129.261 h1.52
  text "REGISTRATION TOLERANCES:" at 272.894,129.134 h1.52
  text "METAL" at 303.368,129.134 h1.52
  text "5" at 318.003,129.134 h1.52
  text "3" at 339.162,129.134 h1.52
  text "MIL" at 342.114,129.134 h1.52
  text "MATERIAL:" at 270.994,123.813 h1.52
  text "FR-4 High Tg" at 296.05,120.249 h1.52
  text "FR-408" at 281.688,120.031 h1.52
  text "X" at 292.153,120.031 h1.52
  text "OTHER" at 319.483,120.031 h1.52
  text "62 MIL (1.6mm) +/-10%" at 289.818,115.898 h1.52
  text "THICKNESS:" at 272.894,115.789 h1.52
  text "X" at 286.563,115.789 h1.52
  text "OTHER" at 322.455,115.789 h1.52
  text "TOLERANCE:" at 272.894,111.776 h1.52
  text "X" at 294.212,111.776 h1.52
  text "ANSI IPC-6012 TYPE 3 CLASS 2" at 298.96,111.776 h1.52
  text "OTHER +/-" at 298.96,107.814 h1.52
  text "BOW & TWIST:" at 272.894,103.826 h1.52
  text "X" at 294.212,103.826 h1.52
  text "ANSI IPC-6012 TYPE 3 CLASS 2" at 298.96,103.826 h1.52
  text "OTHER +/-" at 298.96,99.8 h1.52
  text "DRILLING:" at 270.994,96.282 h1.52
  text "REFERENCE:" at 272.894,93.31 h1.52
  text "X" at 289.359,93.31 h1.52
  text "AS SHOWN" at 294.108,93.31 h1.52
  text "X" at 312.244,93.31 h1.52
  text "NC_DRILL FILES" at 315.724,93.31 h1.52
  text "PTH MIN COPPER THICKNESS:" at 272.894,89.297 h1.52
  text "X" at 307.189,89.297 h1.52
  text "1MIL" at 310.669,89.297 h1.52
  text "OTHER" at 323.293,89.297 h1.52
  text "BOARD FINISH:" at 270.994,85.259 h1.52
  text "SILKSCREEN:" at 274.937,82.261 h1.52
  text "X" at 299.036,82.261 h1.52
  text "TOP" at 302.236,82.261 h1.52
  text "X" at 311.99,82.261 h1.52
  text "BOTTOM" at 315.216,82.261 h1.52
  text "SILKSCREEN COLOR:" at 274.937,78.02 h1.52
  text "X" at 299.01,78.02 h1.52
  text "WHITE" at 302.236,78.02 h1.52
  text "OTHER" at 315.216,78.02 h1.52
  text "SOLDER RESIST COLOR:" at 274.937,73.702 h1.52
  text "X" at 289.358,69.658 h1.52
  text "GREEN" at 292.584,69.658 h1.52
  text "BLUE" at 307.596,69.658 h1.52
  text "OTHER" at 321.261,69.658 h1.52
  text "IMMERSION GOLD (ENIG)" at 297.944,64.87 h1.52
  text "ENEPIG" at 331.917,64.786 h1.52
  text "SURFACE FINISH:" at 270.994,64.761 h1.52
  text "LEAD FREE HASL" at 324,61 h1.52
  text "IMM. TIN/SILVER OR EQUIV" at 279.365,60.773 h1.52
  text "OTHER" at 315.724,60.773 h1.52
  text "X" at 311,60.5 h1.52
  text "ARRAY/PANEL:" at 270.994,56.226 h1.52
  text "CUT AND TRIM PER MECH LAYER 1" at 297.944,56.118 h1.52
  text "N.C. ROUTE" at 297.944,52.264 h1.52
  text "X" at 315.19,52.264 h1.52
  text "V. SCORE" at 319.94,52.264 h1.52
  text "CERTIFICATION:" at 270.994,48.784 h1.52
  text "MATERIALS AND WORKMANSHIP FOR ALL PCBS" at 289.409,48.784 h1.52
  text "TO MEET OR EXCEED THE REQUIREMENTS OF:" at 289.409,46.295 h1.52
  text "X" at 279.923,42.828 h1.52
  text "ANSI IPC-A-600F CLASS ->" at 283.453,42.828 h1.52
  text "X" at 325.085,42.828 h1.52
  text "2" at 328.106,42.828 h1.52
  text "1" at 320.105,42.79 h1.52
  text "3" at 337.098,42.79 h1.52
  text "X" at 279.975,38.777 h1.52
  text "UL 94V-0" at 283.453,38.777 h1.52
  text "X" at 300.6,38.777 h1.52
  text "RoHS" at 304.078,38.777 h1.52
  text "OTHER" at 320.446,38.777 h1.52
  text "PER ORDER" at 330.531,38.777 h1.52
  text "ADDITIONAL REQUIREMENTS:" at 270.994,35.195 h1.52
  text "MICROSECTION:" at 272.894,32.274 h1.52
  text "YES" at 295.899,32.274 h1.52
  text "REQUIRED" at 317.781,28.308 h1.52
  text "BARE BOARD ELEC. TEST:" at 272.894,28.236 h1.52
  text "NONE" at 306.059,28.236 h1.52
  text "X" at 314.555,28.236 h1.52
  text "PER ORDER" at 332.818,28.236 h1.52
  text "MANUFACTURER'S UL:" at 272.894,24.248 h1.52
  text "RAIL" at 302.503,24.139 h1.52
  text "METAL" at 314.995,24.139 h1.52
  text "X" at 324.526,24.13 h1.52
  text "SILK" at 327.992,24.139 h1.52
  text ".Layer_Name" at -2.194,-21.806 h1.52
M11 Gerber Information:
  lines w0.254: -24.267,-23.626 143.373,-23.626 ; -24.267,-18.462 143.424,-18.462 ; -24.267,-13.297 -24.267,-28.791 77.46,-28.791 143.424,-28.791 143.424,-13.297 -24.254,-13.297 -24.254,-28.791 15.764,-28.791 ; 38.344,-28.791 38.344,-13.297 ; 70.526,-18.462 70.526,-13.297 ; 91.862,-18.462 91.862,-13.297 ; 107.661,-28.956 107.661,-23.804
  text "ALL ARTWORK VIEWED FROM TOP SIDE" at -22.654,-16.654 h1.52
  text "BOARD #:" at 40.249,-16.654 h1.52
  text ".PRJ_Number" at 54.105,-16.654 h1.52
  text "REV:" at 75.555,-16.654 h1.52
  text ".PCB_Rev" at 82.959,-16.654 h1.52
  text "SVN REV:" at 96.84,-16.654 h1.52
  text ".VersionControl_RevNumber" at 109.693,-16.654 h1.52
  text "LAYER NAME =" at -22.654,-21.806 h1.52
  text "PLOT NAME =" at -22.654,-27.034 h1.52
  text ".plot_File_Name" at -2.194,-27.034 h1.52
  text "GENERATED    :" at 40.3,-27.034 h1.52
  text ".Print_Date" at 62.385,-27.034 h1.52
  text ".Print_Time" at 80.902,-27.034 h1.52
  text "TEXAS INSTRUMENTS" at 113.02,-27.034 h1.52
M12 Stackup:
  drawing of 191 lines, arcs and shapes, not listed
  text "Layer" at 137.153,182.214 h1.52
  text "Name" at 147.565,182.214 h1.52
  text "Material" at 171.18,182.214 h1.52
  text "Thickness" at 193.018,182.214 h1.52
  text "Constant" at 209.524,182.214 h1.52
  text "Board Layer Stack" at 223.998,182.214 h1.52
  text "1" at 137.153,179.166 h1.52
  text "Top Overlay" at 147.565,179.166 h1.52
  text "2" at 137.153,176.118 h1.52
  text "Top Solder" at 147.565,176.118 h1.52
  text "Solder Resist" at 171.18,176.118 h1.52
  text "0.40mil" at 193.018,176.118 h1.52
  text "3.5" at 209.524,176.118 h1.52
  text "3" at 137.153,173.07 h1.52
  text "Top Layer" at 147.565,173.07 h1.52
  text "Copper" at 171.18,173.07 h1.52
  text "2.76mil" at 193.018,173.07 h1.52
  text "4" at 137.153,170.022 h1.52
  text "Dielectric1" at 147.565,170.022 h1.52
  text "FR-4" at 171.18,170.022 h1.52
  text "59.20mil" at 193.018,170.022 h1.52
  text "4.8" at 209.524,170.022 h1.52
  text "5" at 137.153,166.974 h1.52
  text "Bottom Layer" at 147.565,166.974 h1.52
  text "Copper" at 171.18,166.974 h1.52
  text "2.76mil" at 193.018,166.974 h1.52
  text "6" at 137.153,163.926 h1.52
  text "Bottom Solder" at 147.565,163.926 h1.52
  text "Solder Resist" at 171.18,163.926 h1.52
  text "0.40mil" at 193.018,163.926 h1.52
  text "3.5" at 209.524,163.926 h1.52
  text "7" at 137.153,160.878 h1.52
  text "Bottom Overlay" at 147.565,160.878 h1.52
  text ".Layer_Name" at -2.194,-21.806 h1.52
M13 Component Bodies Top:
  text ".Layer_Name" at -2.194,-21.806 h1.52
M14 Component Bodies Bottom:
  text ".Layer_Name" at -2.194,-21.806 h1.52
M15 Courtyards Top:
  text ".Layer_Name" at -2.194,-21.806 h1.52
M16 Courtyards Bottom:
  text ".Layer_Name" at -2.194,-21.806 h1.52
Drill Drawing:
  lines w0.254: 172.725,81.274 172.725,81.591 173.041,81.907 172.725,82.224 172.725,82.54 173.041,82.54 173.358,82.224 173.674,82.54 173.991,82.54 173.991,82.224 173.674,81.907 173.991,81.591 173.991,81.274 173.674,81.274 173.358,81.591 173.041,81.274 172.725,81.274 ; 172.725,85.704 173.358,85.072 173.991,85.704 173.358,86.337 172.725,85.704 ; 172.725,92.666 172.725,92.983 173.041,93.299 172.725,93.616 172.725,93.932 173.041,93.932 173.358,93.616 173.674,93.932 173.991,93.932 173.991,93.616 173.674,93.299 173.991,92.983 173.991,92.666 173.674,92.666 173.358,92.983 173.041,92.666 172.725,92.666 ; 172.725,96.463 173.991,96.463 173.991,97.729 172.725,97.729 172.725,96.463 ; 172.725,100.577 173.041,100.577 173.358,100.261 173.674,100.577 173.991,100.577 173.674,100.894 173.991,101.21 173.674,101.21 173.358,101.527 173.041,101.21 172.725,101.21 173.041,100.894 172.725,100.577 ; 172.725,107.855 173.991,107.855 173.991,109.121 172.725,109.121 172.725,107.855 ; 172.725,112.918 173.991,112.918 173.358,111.653 172.725,112.918 ; 172.725,115.766 173.041,115.766 173.358,115.45 173.674,115.766 173.991,115.766 173.674,116.083 173.991,116.399 173.674,116.399 173.358,116.716 173.041,116.399 172.725,116.399 173.041,116.083 172.725,115.766 ; 172.725,119.564 173.041,119.564 173.041,119.247 173.674,119.247 173.674,119.564 173.991,119.564 173.991,120.197 173.674,120.197 173.674,120.513 173.041,120.513 173.041,120.197 172.725,120.197 172.725,119.564 ; 172.978,81.527 172.978,81.717 173.168,81.907 172.978,82.097 172.978,82.287 173.168,82.287 173.358,82.097 173.548,82.287 173.737,82.287 173.737,82.097 173.548,81.907 173.737,81.717 173.737,81.527 173.548,81.527 173.358,81.717 173.168,81.527 172.978,81.527 ; 172.978,96.717 173.737,96.717 173.737,97.476 172.978,97.476 172.978,96.717 ; 172.978,115.893 173.168,115.893 173.358,115.703 173.548,115.893 173.737,115.893 173.548,116.083 173.737,116.273 173.548,116.273 173.358,116.463 173.168,116.273 172.978,116.273 173.168,116.083 172.978,115.893 ; 172.978,119.69 173.168,119.69 173.168,119.5 173.548,119.5 173.548,119.69 173.737,119.69 173.737,120.07 173.548,120.07 173.548,120.26 173.168,120.26 173.168,120.07 172.978,120.07 172.978,119.69
  lines w0.305: 171,76.338 224.808,76.338 ; 171,125.703 224.808,125.703 ; 180.411,72.541 180.411,129.5 ; 189.483,72.541 189.483,129.5 ; 206.284,72.541 206.284,129.5 ; 213.503,72.541 213.503,129.5 ; 171,72.541 224.808,72.541 224.808,129.5 171,129.5 171,72.541
  text "Symbol" at 173.278,126.842 h1.83
  text "Quantity" at 181.55,126.842 h1.83
  text "Finished Hole Size" at 190.622,126.842 h1.83
  text "Plated" at 207.424,126.842 h1.83
  text "Hole Type" at 214.642,126.842 h1.83
  text "E" at 173.041,123.361 h1.27
  text "2" at 181.55,123.045 h1.52
  text "3.000mm (118.11mil)" at 190.622,123.045 h1.52
  text "NPTH" at 207.424,123.045 h1.52
  text "Round" at 214.642,123.045 h1.52
  text "4" at 181.55,119.247 h1.52
  text "3.600mm (141.73mil)" at 190.622,119.247 h1.52
  text "NPTH" at 207.424,119.247 h1.52
  text "Round" at 214.642,119.247 h1.52
  text "4" at 181.55,115.45 h1.52
  text "0.750mm (29.53mil)" at 190.622,115.45 h1.52
  text "PTH" at 207.424,115.45 h1.52
  text "Round" at 214.642,115.45 h1.52
  text "4" at 181.55,111.653 h1.52
  text "0.850mm (33.46mil)" at 190.622,111.653 h1.52
  text "PTH" at 207.424,111.653 h1.52
  text "Round" at 214.642,111.653 h1.52
  text "2" at 181.55,107.855 h1.52
  text "0.900mm (35.43mil)" at 190.622,107.855 h1.52
  text "PTH" at 207.424,107.855 h1.52
  text "Round" at 214.642,107.855 h1.52
  text "G" at 173.041,104.375 h1.27
  text "2" at 181.55,104.058 h1.52
  text "0.965mm (38.00mil)" at 190.622,104.058 h1.52
  text "PTH" at 207.424,104.058 h1.52
  text "Round" at 214.642,104.058 h1.52
  text "10" at 181.55,100.261 h1.52
  text "1.000mm (39.37mil)" at 190.622,100.261 h1.52
  text "PTH" at 207.424,100.261 h1.52
  text "Round" at 214.642,100.261 h1.52
  text "6" at 181.55,96.463 h1.52
  text "1.016mm (40.00mil)" at 190.622,96.463 h1.52
  text "PTH" at 207.424,96.463 h1.52
  text "Round" at 214.642,96.463 h1.52
  text "4" at 181.55,92.666 h1.52
  text "1.150mm (45.28mil)" at 190.622,92.666 h1.52
  text "PTH" at 207.424,92.666 h1.52
  text "Round" at 214.642,92.666 h1.52
  text "C" at 173.041,89.185 h1.27
  text "3" at 181.55,88.869 h1.52
  text "1.270mm (50.00mil)" at 190.622,88.869 h1.52
  text "PTH" at 207.424,88.869 h1.52
  text "Round" at 214.642,88.869 h1.52
  text "3" at 181.55,85.072 h1.52
  text "1.300mm (51.18mil)" at 190.622,85.072 h1.52
  text "PTH" at 207.424,85.072 h1.52
  text "Round" at 214.642,85.072 h1.52
  text "2" at 181.55,81.274 h1.52
  text "1.600mm (62.99mil)" at 190.622,81.274 h1.52
  text "PTH" at 207.424,81.274 h1.52
  text "Round" at 214.642,81.274 h1.52
  text "F" at 173.041,77.793 h1.27
  text "2" at 181.55,77.477 h1.52
  text "1.200mm (47.24mil)" at 190.622,77.477 h1.52
  text "PTH" at 207.424,77.477 h1.52
  text "Slot" at 214.642,77.477 h1.52
  text "48 Total" at 181.55,73.68 h1.52
  text ".Layer_Name" at -2.194,-21.806 h1.52

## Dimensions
-16.85,-10.16 to 8.55,-10.16 on M2 Board Dimensions
0,72.5 to 0,18 on M2 Board Dimensions
0,18 to 93.5,18 on M2 Board Dimensions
